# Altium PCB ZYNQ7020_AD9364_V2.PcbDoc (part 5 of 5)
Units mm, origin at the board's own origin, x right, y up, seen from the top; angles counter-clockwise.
Board outline 88.95 x 91.52 mm, 4 copper layers (Top Layer, Layer 1, Layer 2, Bottom Layer), stack 0.603 mm thick; 285 components, 278 nets, 1497 pads, 1247 vias.
Unrouted connection lines stored in the file: 367.
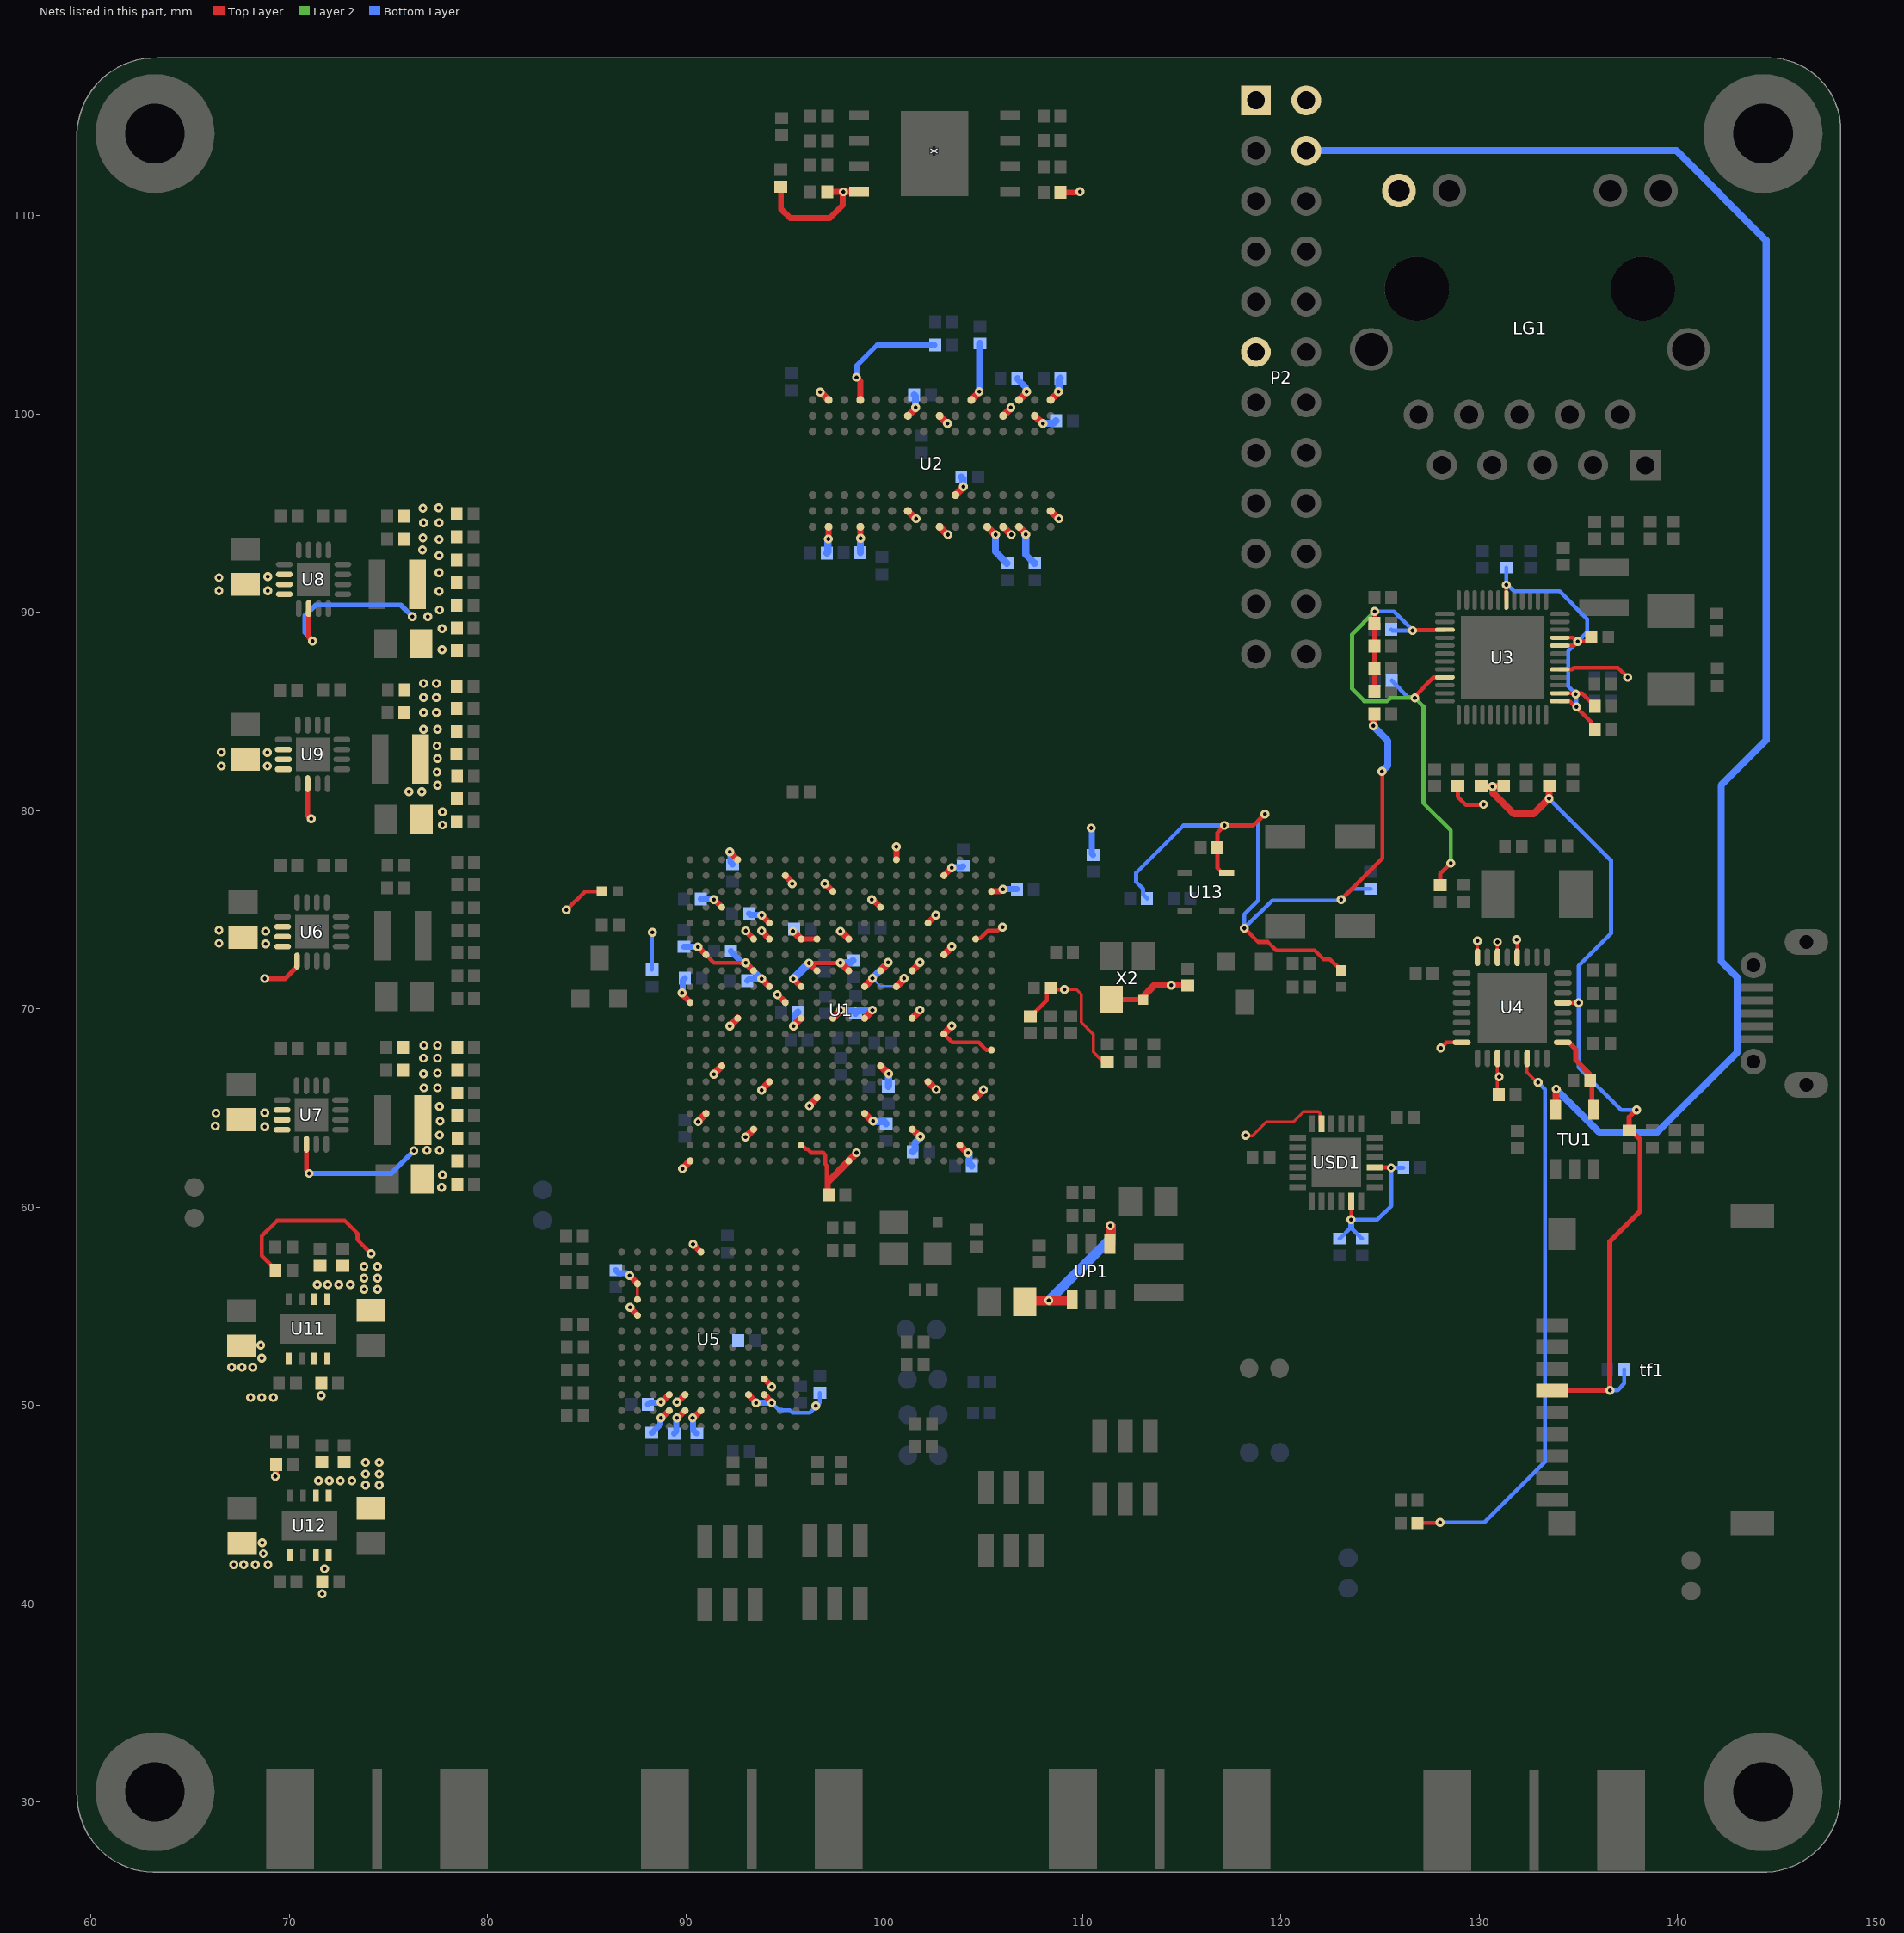
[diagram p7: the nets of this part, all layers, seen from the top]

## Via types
v1: diameter 0.45, hole 0.2, Top Layer to Bottom Layer, tented both sides, 995 vias
v2: diameter 0.406, hole 0.254, Top Layer to Bottom Layer, tented both sides, 118 vias
v3: diameter 1, hole 0.5, Top Layer to Bottom Layer, 116 vias
v4: diameter 0.5, hole 0.3, Top Layer to Bottom Layer, tented both sides, 16 vias
v5: diameter 0.406, hole 0.254, Top Layer to Bottom Layer, 2 vias

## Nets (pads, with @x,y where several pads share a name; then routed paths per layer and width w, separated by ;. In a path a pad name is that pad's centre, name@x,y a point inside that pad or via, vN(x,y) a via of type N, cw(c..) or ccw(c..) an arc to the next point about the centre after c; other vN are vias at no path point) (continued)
VCC_1V5: C8.2 C81.1 C98.1 C99.1 C100.1 C101.1 C102.1 C103.1 C104.1 C105.1 C106.1 C107.1 C108.1 C159.2 C160.2 C161.2 C187.2 C188.2 C189.2 C190.2 C191.2 C192.2 C193.2 L3.2 R3.1 R4.2 R13.1 R14.1 U1.A3 U1.D2 U1.E5 U1.G1 U1.H4 U1.L3 U1.P2 U1.R5 U1.U1 U1.V4 U2.A1 U2.A8 U2.B2 U2.C1 U2.C9 U2.D2 U2.D9 U2.E9 U2.F1 U2.G7 U2.H2 U2.H9 U2.K2 U2.K8 U2.N1 U2.N9 U2.R1 U2.R9 U8.14 | length 46.1
  Top Layer w0.25: U8.14@70.97,90.188 70.97,88.745 v1@71.171,88.544
  Top Layer w0.305: v1@91.417,75.513 U1.V4@91.81,75.12 ; v1@92.217,77.913 U1.U1@92.61,77.52 ; v1@93.817,74.714 U1.R5@94.21,74.32 ; U1.P2@95.01,76.72 v1@95.403,76.328 ; v1@97.017,76.313 U1.L3@97.41,75.92 ; v1(97.18,93.701) 97.18,94.297 U2.R9@97.194,94.31 ; v1(98.603,101.854) 98.794,101.663 U2.N1@98.794,100.711 ; U2.N9@98.795,94.309 98.798,94.306 98.798,93.73 v1(98.802,93.726) ; v1@99.417,75.513 U1.H4@99.81,75.12 ; U1.G1@100.61,77.52 v1(100.609,78.181) ; U1.E5@102.21,74.327 v1@102.603,74.72 ; U1.D2@103.01,76.72 v1@103.403,77.113 ; U1.A3@105.41,75.92 105.418,75.929 105.862,75.929 105.955,76.022 v1(105.994,76.022)
  Top Layer w0.356: v1@96.801,101.104 U2.R1@97.194,100.711 ; U2.K8@101.194,95.111 v1@101.587,94.717 ; U2.K2@101.194,99.911 v1@101.587,100.304 ; U2.H9@102.794,94.31 v1@103.187,93.917 ; U2.H2@102.794,99.911 v1@103.188,99.518 ; U2.G7@103.594,95.91 v1@103.987,96.304 ; U2.F1@104.394,100.711 v1@104.787,101.104 ; U2.E9@105.194,94.31 v1@105.587,93.917 ; U2.D9@105.994,94.31 v1@106.387,93.917 ; U2.D2@105.994,99.911 v1@106.387,100.304 ; U2.C9@106.794,94.31 v1@107.187,93.917 ; U2.C1@106.794,100.711 v1@107.187,101.104 ; U2.B2@107.594,99.911 v1@107.987,99.517 ; U2.A8@108.394,95.111 v1@108.787,94.717 ; U2.A1@108.394,100.711 v1@108.787,101.104
  Bottom Layer w0.25: v1(71.166,88.547) 71.166,88.601 70.79,88.977 70.79,89.84 71.323,90.373 75.616,90.373 v1(76.2,89.789) ; v1(98.603,101.854) 98.619,101.87 98.619,102.454 99.644,103.48 R4.2@102.565,103.48
  Bottom Layer w0.305: C107.1@90.747,75.54 90.76,75.527 91.397,75.527 v1(91.41,75.513) ; v1@92.206,77.909 v1(92.21,77.913) 92.238,77.886 92.238,77.402 C104.1@92.354,77.285 C104.1@92.358,77.289 ; C81.1@93.186,74.803 93.247,74.741 93.782,74.741 v1(93.81,74.714) ; v1(103.403,77.12) 103.43,77.148 103.938,77.148 C106.1@103.988,77.197 ; v1(105.994,76.022) 106.007,76.035 106.674,76.035 C105.1@106.687,76.048 ; C102.1@106.705,101.803 106.705,101.778 107.159,101.324 107.159,101.158 v1(107.187,101.13) ; v1(110.439,79.121) 110.467,79.093 110.467,77.823 R3.1@110.541,77.749
  Bottom Layer w0.356: C161.2@97.097,92.989 97.162,93.054 97.162,93.683 v1(97.18,93.701) ; C160.2@98.799,93.015 98.801,93.016 98.801,93.724 v1(98.802,93.726) ; C103.1@101.505,100.965 101.569,100.901 101.569,100.347 v1(101.587,100.329) ; C100.1@103.886,96.825 103.969,96.742 103.969,96.347 v1(103.987,96.329) ; v1(104.787,101.13) 104.805,101.148 104.805,103.542 C99.1@104.826,103.563 ; v1(105.613,93.917) 105.613,93.059 106.05,92.622 106.05,92.597 106.172,92.475 C159.2@106.197,92.475 ; v1(107.137,93.929) 107.137,92.907 107.569,92.475 C98.1@107.594,92.475 ; v1(108.013,99.517) 108.031,99.535 108.539,99.535 108.661,99.658 C101.1@108.661,99.67 ; v1(108.787,101.13) 108.805,101.148 108.805,101.725 C108.1@108.883,101.803
  other v1: 102.603,74.727 99.365,75.514 95.352,76.302 97.01,76.313 77.699,88.113 77.699,89.179 76.987,89.789 77.572,90.119 77.546,91.059 77.546,91.999 77.546,92.862 76.708,93.142 77.546,93.675 76.733,93.751 103.213,93.917 106.413,93.917 76.759,94.513 77.546,94.513 101.613,94.717 108.813,94.717 76.733,95.25 77.521,95.275 103.189,99.518 106.387,100.329 96.775,101.104
VCC_1V8: C3.2 C61.2 C62.2 C68.2 C69.2 C70.2 C71.2 C72.2 C73.2 C74.2 C80.2 C82.2 C83.2 C85.2 C86.2 C87.2 C89.2 C90.2 C91.2 C96.2 C109.2 C110.2 C141.1 L2.2 R8.1 R10.1 R23.1 R29.2 R30.1 R33.2 R34.1 R39.2 R41.2 R43.2 R45.2 R71.2 U1.A13 U1.B16 U1.C19 U1.D12 U1.E15 U1.F8 U1.F11 U1.F18 U1.G9 U1.H8 U1.H14 U1.J9 U1.J11 U1.J17 U1.K8 U1.K20 U1.L11 U1.M8 U1.M16 U1.N9 U1.N11 U1.N19 U1.P10 U1.R9 U1.R15 U1.T8 U1.T18 U1.U11 U1.V14 U1.W7 U1.W17 U1.Y10 U1.Y20 U3.15 U3.21 U4.8 U4.11 U4.14 U4.28 U4.30 U4.32 U7.14 USD1.5 | length 130.6
  Top Layer w0.152: v1(109.084,70.977) 109.693,70.977 109.931,70.739 109.931,69.317 110.541,68.707 110.541,67.824 110.857,67.508 110.858,67.508 111.227,67.139 R23.1@111.252,67.139 ; v1@118.186,63.602 118.567,63.602 119.26,64.295 120.641,64.295 121.154,64.808 121.894,64.808 121.983,64.719 121.983,64.272 USD1.5@122.057,64.198 ; U4.32@129.924,72.603 v1@129.924,73.403 ; C141.1@130.924,65.659 U4.11@130.924,67.503 ; U4.30@130.924,72.603 v1@130.924,73.343 ; U4.28@131.924,72.603 v1@131.924,73.486 ; U4.14@132.424,67.503 132.424,66.789 v1@132.944,66.269
  Top Layer w0.2: U1.W7@91.01,72.72 91.417,72.314 v1(93.01,72.314)
  Top Layer w0.203: U1.N19@95.81,63.12 95.85,63.12 96.043,62.927 96.128,62.927 96.313,62.742 96.913,62.742 97.032,62.623 97.032,62.164 97.095,62.1 97.095,60.789 97.148,60.789 97.187,60.828 97.187,61.298 ; U1.D12@103.01,68.72 103.43,68.301 104.765,68.301 105.141,67.924 105.406,67.924 U1.A13@105.41,67.92 ; R29.2@107.373,69.618 107.398,69.618 108.202,70.421 108.202,70.82 108.358,70.977 v1(109.084,70.977) ; R45.2@124.722,86.012 R43.2@124.722,87.155 R39.2@124.722,88.298 R41.2@124.722,89.441 124.739,89.459 v1(124.739,90.043) ; v1(126.644,89.078) 126.67,89.103 128.261,89.103 U3.15@128.276,89.118 ; v1(126.765,85.689) 126.765,85.776 127.704,86.715 128.272,86.715 U3.21@128.276,86.718 ; R71.2@126.892,44.069 128.016,44.069 v1@128.041,44.094 ; R33.2@128.041,76.237 128.041,76.81 v1(128.575,77.343) ; v1(128.067,68.021) 128.349,68.303 U4.8@129.124,68.303 ; R34.1@128.931,81.218 128.931,80.692 129.337,80.286 130.197,80.286 v1(130.226,80.315)
  Top Layer w0.22: v1(96.21,72.306) 96.217,72.314 v1(97.791,72.314)
  Top Layer w0.25: U7.14@70.858,63.17 70.858,61.831 v1(70.993,61.697)
  Top Layer w0.305: v1(89.81,70.792) 89.838,70.764 89.838,70.705 90.21,70.333 U1.Y10@90.21,70.32 ; v1@90.617,73.114 U1.W7@91.01,72.72 ; v1@93.017,72.314 U1.T8@93.41,71.92 ; v1@93.817,71.513 U1.R9@94.21,71.12 ; v1@94.617,70.714 U1.P10@95.01,70.32 ; v1@95.417,71.513 U1.N9@95.81,71.12 ; v1(96.21,72.306) 96.217,72.306 96.603,71.92 U1.M8@96.61,71.92
  Top Layer w0.35: 97.187,61.298 U1.K20@98.21,62.32
  Top Layer w0.356: v1@89.83,61.941 U1.Y20@90.21,62.32 U1.Y20@90.223,62.334 ; v1@90.616,64.327 U1.W17@91.01,64.72 ; v1@91.417,66.727 U1.V14@91.81,67.12 ; v1(92.217,69.123) 92.217,69.127 U1.U11@92.61,69.52 ; v1(93.006,63.536) 93.026,63.536 U1.T18@93.41,63.92 U1.T18@93.423,63.934 ; v1@93.817,65.927 U1.R15@94.21,66.32 ; v1(95.418,69.13) 95.419,69.13 U1.N11@95.81,69.52 ; v1(96.221,65.106) 96.221,65.131 U1.M16@96.61,65.52 ; U1.L11@97.41,69.52 v1@97.803,69.914 ; v1@97.817,72.314 U1.K8@98.21,71.92 ; U1.K20@98.21,62.32 v1@98.603,62.714 ; U1.J17@99.01,64.72 v1@99.403,64.327 ; U1.J11@99.01,69.52 v1@99.403,69.914 ; U1.J9@99.01,71.12 v1@99.403,71.514 ; U1.H14@99.81,67.12 v1@100.203,66.727 ; U1.H8@99.81,71.92 v1@100.203,72.314 ; U1.G9@100.61,71.12 v1@101.003,71.514 ; U1.F18@101.41,63.92 101.43,63.92 101.803,63.547 v1(101.829,63.547) ; U1.F11@101.41,69.52 v1@101.803,69.914 ; U1.F8@101.41,71.92 v1@101.816,72.326 ; U1.E15@102.21,66.32 v1@102.603,65.927 ; U1.D12@103.01,68.72 v1@103.403,69.114 ; U1.C19@103.81,63.12 v1@104.203,62.727 ; U1.B16@104.61,65.52 105.003,65.914 v1(105.003,65.924)
  Layer 2 w0.203: v1(124.739,90.043) 123.596,88.9 123.596,86.131 124.206,85.522 125.368,85.522 125.536,85.689 v1(126.765,85.689) 127.196,85.257 127.196,80.372 128.575,78.994 v1(128.575,77.343) ; v1@130.142,80.34 130.168,80.315 v1(130.226,80.315)
  Bottom Layer w0.107: v1(99.403,71.539) 99.797,71.145 100.61,71.145 v1(101.003,71.539)
  Bottom Layer w0.203: v1(124.739,90.043) 125.705,90.043 126.644,89.103 v1(126.644,89.078) 125.63,89.078 C110.2@125.572,89.136 ; C109.2@125.597,86.571 125.597,86.546 126.414,85.729 126.725,85.729 v1(126.765,85.689) ; v1(128.032,44.088) 130.27,44.088 133.325,47.142 133.325,65.933 v1(132.974,66.284)
  Bottom Layer w0.25: v1(70.993,61.697) 75.133,61.697 v1(76.276,62.84)
  Bottom Layer w0.305: v1(89.81,70.792) 89.838,70.819 89.838,71.441 C82.2@89.948,71.552 ; C83.2@89.891,73.133 89.9,73.124 90.6,73.124 v1(90.61,73.114) ; C73.2@92.271,72.923 92.271,72.898 v1@92.828,72.341 ; v1(93.01,72.314) v1(93.81,71.513) 93.782,71.486 93.152,71.486 C72.2@93.091,71.425
  Bottom Layer w0.356: v1(95.418,69.13) 95.418,69.156 95.527,69.265 95.527,69.702 C96.2@95.65,69.825 ; v1(97.791,72.314) 97.809,72.332 98.323,72.332 C70.2@98.425,72.434 ; v1(97.803,69.939) 97.829,69.939 97.865,69.903 98.43,69.903 C69.2@98.552,69.781 98.674,69.903 99.341,69.903 99.377,69.939 v1(99.403,69.939) ; v1(99.403,71.539) v1(100.203,72.339) ; v1(99.429,64.327) 99.447,64.309 99.997,64.309 C80.2@100.101,64.204 ; C68.2@100.203,66.084 100.216,66.097 100.216,66.714 v1(100.229,66.727) ; C90.2@101.429,62.789 101.551,62.911 101.551,63.244 101.829,63.522 v1(101.829,63.547) ; v1(104.229,62.727) 104.229,62.701 104.29,62.64 104.29,62.2 C85.2@104.413,62.078
  Bottom Layer w0.4: v1(95.41,71.513) 95.414,71.513 96.207,72.306 v1(96.21,72.306)
  other v1: 77.673,60.985 77.724,61.62 89.83,61.936 98.603,62.739 76.937,62.865 77.572,62.865 77.572,63.627 118.23,63.615 90.616,64.302 77.597,64.338 77.572,65.075 93.817,65.902 102.629,65.927 76.784,66.015 77.47,66.015 131.013,66.573 91.417,66.701 76.759,66.726 77.47,66.751 76.759,67.513 77.47,67.513 76.784,68.148 77.47,68.148 103.403,69.139 101.803,69.939 94.61,70.714 101.803,72.339 130.93,73.368 129.914,73.419 131.895,73.495
VCC_3V3: *.8 C9.2 C20.2 C21.2 C25.2 C26.2 C75.2 C76.2 C77.2 C78.2 C113.2 C114.2 C115.2 C116.2 C120.1 C132.1 C133.1 C134.1 C138.1 C139.1 C181.1 C182.1 C183.1 CP1.2 DONE.1 L4.2 LG1.14 P2.1 P2.6 R15.1 R16.1 R19.1 R27.2 R35.1 R38.1 R46.1 R47.1 R48.1 R55.1 R57.1 R59.2 R63.1 R68.2 tf1.4 U1.B6 U1.D7 U1.K6 U1.M6 U1.N6 U1.R6 U1.T6 U3.6 U3.37 U3.38 U3.41 U3.44 U3.45 U4.21 U9.14 U11.5 U11.7 U11.8 U12.5 U12.7 U12.8 U13.4 UP1.1 UP1.4 USD1.17 USD1.21 USR_LED.1 X2.1 X2.4 | length 150.6
  Top Layer w0.2: v1(118.161,74.066) 118.855,73.372 119.344,73.372 119.767,72.949 121.706,72.949 122.161,72.493 122.484,72.493 USR_LED.1@123.038,71.94
  Top Layer w0.203: v1(83.972,74.981) 84.912,75.921 DONE.1@85.747,75.921 ; U1.B6@104.61,73.52 104.638,73.548 104.841,73.548 105.235,73.942 105.727,73.942 105.902,74.117 v1(105.969,74.117) ; v1(117.164,79.249) 118.619,79.249 v1(119.202,79.832) ; v1@117.17,79.248 116.808,78.886 C132.1@116.808,78.13 116.808,77.096 117.043,76.86 U13.4@117.272,76.86 ; v1(123.038,75.514) 125.12,77.597 v1@125.12,81.94 ; v1@123.556,59.385 USD1.17@123.556,60.3 ; USD1.21@124.757,61.999 125.575,61.999 v1@125.578,62.001 ; v1@131.369,91.415 131.376,91.408 U3.6@131.376,90.618 ; U3.37@134.076,85.518 134.079,85.515 134.584,85.515 135.642,84.458 135.642,84.305 C115.2@135.84,84.107 ; U3.38@134.076,85.918 135.197,85.918 135.84,85.275 C116.2@135.84,85.25 ; U3.41@134.076,87.118 134.079,87.121 134.693,87.121 134.774,87.202 137.004,87.202 v1(137.49,86.716) ; U3.44@134.076,88.318 134.079,88.321 134.778,88.321 134.909,88.452 v1@134.909,88.544 ; U3.45@134.076,88.718 134.079,88.715 134.738,88.715 v1@134.909,88.544 ; U4.21@134.224,70.303 v1(135.022,70.303) ; C114.2@135.661,88.748 135.661,88.743 135.463,88.544 v1@134.909,88.544
  Top Layer w0.25: U9.14@70.922,81.354 70.922,79.751 v1(71.095,79.578) ; X2.4@111.455,70.46 112.903,70.46 X2.1@113.055,70.46 ; tf1.4@133.685,50.741 133.693,50.749 136.585,50.749 v1(136.594,50.758) 136.594,58.26 138.118,59.784 138.118,63.406 R68.2@137.643,63.881 ; R68.2@137.566,63.856 137.566,64.538 137.922,64.894 v1@137.922,64.948
  Top Layer w0.254: U1.N6@95.81,73.52 U1.M6@96.61,73.52
  Top Layer w0.3: R48.1@94.793,111.462 94.793,110.338 95.25,109.88 97.257,109.88 97.907,110.531 97.907,111.179 v1(97.935,111.206) ; C133.1@97.13,111.201 97.135,111.206 v1(97.935,111.206) ; *.8@98.74,111.211 98.735,111.206 v1(97.935,111.206) ; R59.2@108.883,111.176 v1@109.804,111.176
  Top Layer w0.305: v1(93.01,73.936) 93.01,73.928 93.41,73.528 U1.T6@93.41,73.52 ; v1(93.81,73.936) 93.81,73.928 94.21,73.528 U1.R6@94.21,73.52
  Top Layer w0.356: v1@95.417,73.914 U1.N6@95.81,73.52 ; v1@97.817,73.914 U1.K6@98.21,73.52 ; U1.D7@103.01,72.72 v1@103.403,73.114 ; X2.1@112.903,70.46 112.975,70.532 113.64,71.196 v1(114.469,71.196) 115.297,71.196 C120.1@115.316,71.178 ; v1(124.663,84.277) 124.663,84.811 R38.1@124.722,84.869 ; R27.2@130.1,81.218 v1(130.671,81.218) ; R35.1@131.243,81.218 v1(130.671,81.218) ; R46.1@133.554,81.218 133.528,81.192 133.528,80.62 132.745,79.837 131.748,79.837 130.689,80.895 130.689,81.2 v1(130.671,81.218)
  Top Layer w0.5: CP1.2@107.088,55.22 107.149,55.28 v1(108.301,55.28) 109.454,55.28 109.479,55.305 UP1.1@109.479,55.341 ; UP1.4@111.379,58.141 111.404,58.166 v1(111.404,59.055)
  Bottom Layer w0.2: v1(119.202,79.832) 118.847,79.477 118.847,75.463 118.161,74.778 v1(118.161,74.066) 119.563,75.469 122.992,75.469 v1(123.038,75.514)
  Bottom Layer w0.203: R55.1@88.29,71.977 88.29,73.838 v1@88.316,73.863 ; R47.1@113.252,75.565 113.053,75.763 113.053,76.05 112.703,76.4 112.703,76.86 115.092,79.249 v1(117.164,79.249) ; C138.1@122.961,58.413 122.986,58.413 123.501,58.928 123.501,59.316 v1(123.549,59.363) ; v1(123.038,75.514) 123.578,76.054 R19.1@124.536,76.054 ; C134.1@124.104,58.413 124.079,58.413 123.596,58.897 123.596,59.316 v1(123.549,59.363) ; C139.1@126.187,61.976 126.184,61.979 v1(125.57,61.979) 125.57,60.064 124.869,59.363 v1(123.549,59.363) ; C113.2@131.369,92.253 131.371,92.251 v1(131.371,91.38) 131.437,91.38 131.759,91.059 134.061,91.059 135.458,89.662 135.458,89.012 v1(134.968,88.522) 134.493,88.047 134.493,86.258 v1(134.874,85.877) 134.896,85.856 134.896,85.242 v1(134.918,85.22) ; v1(133.53,80.611) 136.652,77.49 136.652,73.787 135.022,72.157 v1(135.022,70.303) 135.022,67.035 137.16,64.897 v1(137.947,64.897) ; v1@136.594,50.759 136.985,50.759 137.324,51.098 R63.1@137.324,51.816
  Bottom Layer w0.356: v1(124.663,84.277) 124.663,84.252 125.4,83.515 125.4,82.271 v1(125.095,81.966)
  Bottom Layer w0.5: v1(108.301,55.28) 111.404,58.383 v1(111.404,59.055)
  other v1: 71.653,40.488 71.78,41.758 67.191,41.971 67.699,41.971 68.283,41.971 68.918,41.971 68.682,42.52 68.631,43.078 68.047,50.394 68.605,50.394 69.19,50.394 71.603,50.495 67.081,51.918 67.615,51.918 68.148,51.918 68.605,52.375 68.555,53.035 103.403,73.139 88.309,73.864 95.391,73.914 97.791,73.914 77.724,79.273 77.724,79.934 76.022,80.95 76.683,80.95 77.47,81.28 77.445,81.94 77.47,82.626 77.445,83.261 76.759,84.099 77.47,84.099 76.759,84.938 77.419,84.938 76.759,85.7 77.419,85.7 76.759,86.411 77.419,86.411 109.864,111.212
VCC_IN: C4.2 C5.2 C10.2 C12.2 P2.13 P2.14 TU1.5 U6.10 U6.11 U6.12 U6.13 U7.10 U7.11 U7.12 U8.10 U8.11 U8.12 U9.10 U9.11 U9.12 | length 82.2
  Top Layer w0.25: v1(68.758,71.526) 69.783,71.526 70.383,72.127 U6.13@70.383,72.413
  Top Layer w0.356: TU1.5@133.873,64.905 v1@133.873,65.954
  Bottom Layer w0.356: P2.14@121.285,113.284 139.954,113.284 144.475,108.763 144.475,83.541 142.215,81.28 142.215,72.39 143.027,71.577 143.027,67.818 138.989,63.779 136.057,63.779 v1(133.886,65.951)
  other v1: 68.758,64.059 66.269,64.084 66.294,64.719 68.758,64.745 68.809,73.279 66.446,73.304 68.809,73.914 66.446,73.965 66.573,82.245 68.885,82.245 68.885,82.931 66.573,82.956 66.446,91.084 68.91,91.084 66.446,91.745 68.91,91.796
VDD_DIG: C22.2 C23.2 C24.2 C172.1 C177.1 R22.1 RX4.2 U5.B8 U5.D2 U5.D3 U5.E3 U5.F12 U5.K4 U12.1 U12.2 | length 5.5
  Top Layer w0.3: v1(69.291,46.406) 69.311,46.425 69.311,46.996 R22.1@69.33,47.015
  Top Layer w0.305: v1@87.181,54.907 U5.B8@87.554,54.534 ; v1@88.767,49.361 U5.D2@89.141,49.734 ; v1@88.767,50.161 U5.D3@89.141,50.534 ; v1@89.567,50.161 U5.E3@89.941,50.534 ; v1(90.357,58.131) U5.F12@90.754,57.734 ; U5.K4@93.954,51.334 v1@94.328,50.961
  Bottom Layer w0.3: C177.1@88.08,50.038 88.175,50.132 88.707,50.132 v1(88.735,50.161) ; C172.1@88.265,48.609 88.29,48.609 88.707,49.026 88.707,49.332 v1(88.735,49.361)
  other v1: 73.838,45.974 74.524,45.974 71.476,46.203 72.009,46.203 72.568,46.203 73.152,46.203 73.838,46.533 74.524,46.533 73.838,47.117 74.524,47.117 89.536,50.161 94.328,50.929 87.181,54.939
VDDA_RX_LO: C17.2 C18.2 C19.2 C166.1 C170.1 C174.1 C175.1 R21.1 U5.B9 U5.B10 U5.E2 U5.F2 U5.J3 U5.K3 U11.1 U11.2 | length 18.9
  Top Layer w0.15: U5.B9@87.554,55.334 U5.B10@87.554,56.134
  Top Layer w0.2: R21.1@69.298,56.82 69.298,56.845 68.605,57.537 68.605,58.536 69.379,59.309 72.799,59.309 73.434,58.674 73.434,58.341 v1(74.117,57.658)
  Top Layer w0.305: v1(87.16,56.544) 87.16,56.536 87.55,56.147 U5.B10@87.554,56.147 ; v1@89.567,49.361 U5.E2@89.941,49.734 ; v1@90.367,49.361 U5.F2@90.74,49.734 ; U5.J3@93.154,50.534 v1@93.527,50.161 ; U5.K3@93.954,50.534 v1@94.328,50.161
  Bottom Layer w0.2: v1(94.328,50.129) 94.346,50.129 94.346,50.11 94.701,49.756 95.239,49.756 95.375,49.619 96.254,49.619 96.491,49.856 v1(96.546,49.963) ; v1@96.572,49.937 96.749,50.114 C166.1@96.749,50.629
  Bottom Layer w0.305: C170.1@86.462,56.813 86.609,56.665 87,56.665 87.121,56.544 v1(87.16,56.544) ; C175.1@89.408,48.577 89.508,48.676 89.508,49.333 v1(89.536,49.361) ; v1(90.335,49.361) 90.363,49.333 90.363,48.771 90.378,48.756 90.378,48.731 90.526,48.583 C174.1@90.551,48.583 ; v1(93.527,50.129) v1(94.328,50.129)
  other v1: 73.762,55.855 74.447,55.855 71.399,56.083 71.933,56.083 72.492,56.083 73.076,56.083 73.762,56.413 74.447,56.413 73.762,56.998 74.447,56.998
VUSB_V_EN: R69.1 TU1.4 U4.17 | length 4.2
  Top Layer w0.254: U4.17@134.224,68.303 134.527,68.303 134.874,67.956 134.874,67.412 135.582,66.704 135.582,66.392 R69.1@135.604,66.37 135.688,66.286 135.688,64.99 TU1.4@135.773,64.905
pads on no net: *.9 LG1. tf1.0 tf1.11 tf1.12 U1.A20 U1.B5 U1.B9 U1.B13 U1.B19 U1.B20 U1.C6 U1.C20 U1.D9 U1.D18 U1.D19 U1.E6 U1.E8 U1.E9 U1.E17 U1.E18 U1.E19 U1.F16 U1.F17 U1.F19 U1.G14 U1.G15 U1.G17 U1.G18 U1.G19 U1.H15 U1.H16 U1.H17 U1.H18 U1.J14 U1.J15 U1.J16 U1.J18 U1.J19 U1.K9 U1.K14 U1.K16 U1.K17 U1.K18 U1.K19 U1.L10 U1.L14 U1.L15 U1.L16 U1.L17 U1.L19 U1.L20 U1.M14 U1.M15 U1.M17 U1.M18 U1.M19 U1.M20 U1.N15 U1.N16 U1.P1 U1.P3 U1.R1 U1.R2 U1.R3 U1.T1 U1.T2 U1.T4 U1.T5 U1.T9 U1.U2 U1.U3 U1.U4 U1.U5 U1.U7 U1.U8 U1.U9 U1.U10 U1.V1 U1.V2 U1.V3 U1.V5 U1.V6 U1.V7 U1.V8 U1.V10 U1.V11 U1.W1 U1.W3 U1.W4 U1.W5 U1.W6 U1.W8 U1.W9 U1.W10 U1.W11 U1.W15 U1.Y1 U1.Y2 U1.Y3 U1.Y4 U1.Y6 U1.Y7 U1.Y8 U1.Y9 U1.Y11 U1.Y12 U1.Y13 U2.J1 U2.J9 U2.L1 U2.L9 U2.M7 U3.12 U3.46 U4.12 U4.15 U4.16 U5.A3 U5.B3 U5.B4 U5.B5 U5.B6 U5.B7 U5.C3 U5.L5 U5.M3 U5.M11 UP1.5 USD1.8 USD1.10 USD1.12 USD1.13 USD1.14 USD1.15 X4.1
copper on no net:
  other v1: 103.48,111.735 101.676,111.76 101.651,114.427 103.48,114.427
  other v3: 63.221,28.305 63.221,28.305 144.323,28.305 144.323,28.305 62.379,28.473 62.379,28.473 64.063,28.473 64.063,28.473 143.481,28.473 143.481,28.473 145.165,28.473 145.165,28.473 61.665,28.95 61.665,28.95 64.776,28.95 64.776,28.95 142.767,28.95 142.767,28.95 145.878,28.95 145.878,28.95 61.188,29.663 61.188,29.663 65.253,29.663 142.29,29.663 142.29,29.663 146.355,29.663 61.021,30.505 61.021,30.505 65.421,30.505 142.123,30.505 142.123,30.505 146.523,30.505 61.188,31.347 61.188,31.347 65.253,31.347 142.29,31.347 142.29,31.347 146.355,31.347 61.665,32.061 61.665,32.061 64.776,32.061 64.776,32.061 142.767,32.061 142.767,32.061 145.878,32.061 145.878,32.061 62.379,32.538 62.379,32.538 64.063,32.538 64.063,32.538 143.481,32.538 143.481,32.538 145.165,32.538 145.165,32.538 63.221,32.705 63.221,32.705 144.323,32.705 144.323,32.705 63.221,111.948 63.221,111.948 144.323,111.948 144.323,111.948 62.379,112.115 62.379,112.115 64.063,112.115 64.063,112.115 143.481,112.115 143.481,112.115 145.165,112.115 145.165,112.115 61.665,112.592 61.665,112.592 64.776,112.592 64.776,112.592 142.767,112.592 142.767,112.592 145.878,112.592 145.878,112.592 61.188,113.306 61.188,113.306 65.253,113.306 142.29,113.306 142.29,113.306 146.355,113.306 61.021,114.148 61.021,114.148 65.421,114.148 142.123,114.148 142.123,114.148 146.523,114.148 61.188,114.99 61.188,114.99 65.253,114.99 142.29,114.99 142.29,114.99 146.355,114.99 61.665,115.703 61.665,115.703 64.776,115.703 64.776,115.703 142.767,115.703 142.767,115.703 145.878,115.703 145.878,115.703 62.379,116.18 62.379,116.18 64.063,116.18 64.063,116.18 143.481,116.18 143.481,116.18 145.165,116.18 145.165,116.18 63.221,116.348 63.221,116.348 144.323,116.348 144.323,116.348

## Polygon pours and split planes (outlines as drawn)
GND on Top Layer "GND_L01_P155" (solid, pour order 155): 71.222,63.475 71.984,63.475 71.984,62.789 72.644,62.128 75.514,62.128 75.514,60.655 72.619,60.655 71.222,62.052
GND on Top Layer "GND_L01_P147" (solid, pour order 147): 141.478,41.478 139.776,41.478 139.548,41.707 139.548,42.926 139.827,43.205 141.3,43.205 141.681,42.824 141.681,41.656
GND on Top Layer "GND_L01_P146" (solid, pour order 146): 119.304,51.003 119.304,52.705 119.532,52.934 120.752,52.934 121.031,52.654 121.031,51.181 120.65,50.8 119.482,50.8
GND on Top Layer "GND_L01_P145" (solid, pour order 145): 65.964,60.274 64.262,60.274 64.033,60.503 64.033,61.722 64.313,62.001 65.786,62.001 66.167,61.62 66.167,60.452
RFGND on Top Layer "RFGND_L01_P142" (solid, pour order 142): 146.253,34.646 143.013,34.646 ccw(c143.013,32.106) 141.217,33.902 140.538,33.223 ccw(c141.029,32.733) 140.335,32.733 140.335,27.94 cw(c138.618,27.94) 139.832,26.726 139.802,26.695 cw(c139.556,26.941) 139.556,26.594 67.278,26.594 cw(c67.278,27.374) 66.726,26.822 cw(c66.91,27.006) 66.65,27.006 66.65,31.13 ccw(c64.11,31.13) 65.906,32.926 65.024,33.807 ccw(c63.859,32.642) 63.859,34.29 62.154,34.29 cw(c62.154,36.007) 60.94,34.793 60.604,35.128 cw(c61.463,35.987) 60.249,35.987 60.249,56.682 cw(c62.789,56.682) 60.993,58.478 61.824,59.309 cw(c63.602,57.531) 63.602,60.046 115.026,60.046 cw(c115.026,57.506) 116.822,59.302 118.28,57.843 cw(c116.485,56.047) 119.024,56.047 119.024,45.782 ccw(c121.564,45.782) 119.768,43.985 121.59,42.164 ccw(c123.368,43.942) 123.368,41.427 142.322,41.427 146.631,41.427 cw(c141.432,37.309) 147.879,35.752 147.456,35.197 147.355,35.087 cw(c146.228,36.214) 146.228,34.62
VCC_3V3 on Top Layer "VCC_3V3_L01_P130" (solid, pour order 130): 71.603,50.089 67.767,50.089 67.716,50.14 67.716,50.622 67.767,50.673 71.222,50.673 71.603,51.054
VCC_3V3 on Top Layer "VCC_3V3_L01_P091" (solid, pour order 91): 71.12,52.756 72.085,52.756 72.085,51.587 71.907,51.41 71.907,50.089 71.298,50.089 71.298,51.867 71.12,52.045
GND on Top Layer "GND_L01_P125" (solid, pour order 125): 68.301,65.634 68.301,67.437 67.996,67.742 66.345,67.742 66.167,67.564 66.167,65.837 66.37,65.634
GND on Top Layer "GND_L01_P124" (solid, pour order 124): 68.377,74.803 68.377,76.606 68.072,76.911 66.421,76.911 66.243,76.733 66.243,75.006 66.446,74.803
GND on Top Layer "GND_L01_P123" (solid, pour order 123): 68.478,83.769 68.478,85.573 68.174,85.877 66.523,85.877 66.345,85.7 66.345,83.972 66.548,83.769
GND on Top Layer "GND_L01_P122" (solid, pour order 122): 68.504,92.608 68.504,94.412 68.199,94.717 66.548,94.717 66.37,94.539 66.37,92.812 66.573,92.608
VCC_IN on Top Layer "VCC_IN_L01_P121" (solid, pour order 121): 69.952,65.024 69.952,63.754 65.989,63.754 65.989,65.024
VCC_IN on Top Layer "VCC_IN_L01_P120" (solid, pour order 120): 70.053,74.27 70.053,73 66.142,73 66.142,74.27
VCC_IN on Top Layer "VCC_IN_L01_P119" (solid, pour order 119): 70.079,83.21 70.079,81.94 66.294,81.94 66.294,83.21
VCC_IN on Top Layer "VCC_IN_L01_P118" (solid, pour order 118): 70.028,92.05 70.028,90.78 66.167,90.78 66.167,92.05
GND on Top Layer "GND_L01_P116" (solid, pour order 116): 71.247,72.695 72.009,72.695 72.009,72.085 72.746,71.349 75.489,71.349 75.489,69.875 72.593,69.875 71.247,71.222
GND on Top Layer "GND_L01_P115" (solid, pour order 115): 71.272,81.686 72.06,81.686 72.06,80.975 72.746,80.289 75.438,80.289 75.438,78.816 72.542,78.816 71.272,80.086
GND on Top Layer "GND_L01_P114" (solid, pour order 114): 71.323,90.5 72.085,90.5 72.085,89.865 72.796,89.154 75.438,89.154 75.438,87.681 72.542,87.681 71.323,88.9
NetL2_1 on Top Layer "NETL2_1_L01_P113" (solid, pour order 113): 72.314,65.024 72.314,63.754 73.635,63.754 74.244,63.144 75.108,63.144 75.108,65.634 74.27,65.634 73.66,65.024
NetL1_1 on Top Layer "NETL1_1_L01_P112" (solid, pour order 112): 72.314,74.27 72.314,73 73.711,73 74.27,72.441 75.133,72.441 75.133,74.93 74.295,74.93 73.635,74.27
NetL4_1 on Top Layer "NETL4_1_L01_P111" (solid, pour order 111): 72.339,83.21 72.339,81.94 73.533,81.94 74.117,81.356 74.981,81.356 74.981,83.845 74.143,83.845 73.508,83.21
NetL3_1 on Top Layer "NETL3_1_L01_P110" (solid, pour order 110): 72.39,92.05 72.39,90.78 73.381,90.78 73.99,90.17 74.854,90.17 74.854,92.659 74.016,92.659 73.406,92.05
GND on Top Layer "GND_L01_P109" (solid, pour order 109): 70.104,68.351 72.009,68.351 72.009,67.361 71.501,66.853 71.501,65.786 70.206,65.786 70.206,66.853 70.104,66.954
GND on Top Layer "GND_L01_P108" (solid, pour order 108): 70.104,77.546 72.034,77.546 72.034,76.53 71.526,76.022 71.526,75.032 70.231,75.032 70.231,76.048 70.104,76.175
GND on Top Layer "GND_L01_P107" (solid, pour order 107): 72.009,86.411 70.079,86.411 70.079,85.344 70.282,85.141 70.282,83.972 71.552,83.972 71.552,84.988 72.009,85.446
GND on Top Layer "GND_L01_P106" (solid, pour order 106): 70.333,92.837 71.603,92.837 71.603,93.828 72.009,94.234 72.009,95.174 70.104,95.174 70.104,93.929 70.333,93.701
GND on Top Layer "GND_L01_P105" (solid, pour order 105): 78.892,69.419 78.892,68.504 79.045,68.351 79.045,60.884 79.197,60.731 80.467,60.731 82.829,63.094 82.829,69.673
GND on Top Layer "GND_L01_P104" (solid, pour order 104): 83.194,83.398 82.333,82.536 81.798,83.285 82.412,83.49
GND on Top Layer "GND_L01_P103" (solid, pour order 103): 78.892,95.352 79.273,95.733 82.474,95.733 82.702,95.961 82.829,95.834 82.829,69.571 82.093,68.834 79.375,68.834 78.892,69.317
GND on Top Layer "Top Layer-GND" (solid, pour order 76): 88.154,83.582 88.154,92.024 89.002,92.812 89.029,98.559 94.302,103.832 101.076,103.832 102.925,101.983 109.574,101.983 112.973,98.584 112.973,81.038 107.949,76.014 107.949,75.794 111.827,75.794 112.098,76.064 112.098,77.089 115.646,80.637 115.646,104.008 110.536,109.118 90.297,109.118 82.677,101.498 82.677,83.109 87.681,83.109
VCC_1V5 on Top Layer "VCC_1V5_L01_P102" (solid, pour order 102): 78.791,87.655 75.87,87.655 75.794,87.732 75.794,92.735 75.413,93.116 75.413,95.631 75.514,95.733 78.74,95.733 78.791,95.682
VCC_3V3 on Top Layer "VCC_3V3_L01_P101" (solid, pour order 101): 75.794,78.689 75.717,78.765 75.717,84.099 75.438,84.379 75.438,86.69 75.565,86.817 78.791,86.817 78.867,86.741 78.867,78.791 78.765,78.689
VCC_1V0 on Top Layer "VCC_1V0_L01_P100" (solid, pour order 100): 75.971,69.698 75.819,69.85 75.819,75.133 75.413,75.54 75.413,78.105 75.59,78.283 78.791,78.283 78.791,69.774 78.715,69.698
VCC_1V8 on Top Layer "VCC_1V8_L01_P098" (solid, pour order 98): 78.816,60.757 77.546,60.757 77.419,60.63 75.971,60.63 75.87,60.731 75.87,65.862 75.336,66.396 75.336,68.402 75.463,68.529 78.791,68.529 78.816,68.504
VCC_3V3 on Top Layer "VCC_3V3_L01_P093" (solid, pour order 93): 70.206,42.748 69.342,42.748 68.428,43.663 66.878,43.663 66.878,41.707 70.206,41.707
VCC_3V3 on Top Layer "VCC_3V3_L01_P092" (solid, pour order 92): 70.129,52.654 69.266,52.654 68.351,53.569 66.802,53.569 66.802,51.638 70.129,51.638
VCC_3V3 on Top Layer "VCC_3V3_L01_P090" (solid, pour order 90): 71.171,42.774 72.136,42.774 72.136,41.605 71.958,41.427 71.958,40.208 71.349,40.208 71.349,41.986 71.171,42.164
VDD_DIG on Top Layer "VDD_DIG_L01_P089" (solid, pour order 89): 71.145,45.085 71.145,47.447 74.727,47.447 74.854,47.32 74.854,44.221 73.254,44.221 72.39,45.085
VDDA_RX_LO on Top Layer "VDDA_RX_LO_L01_P088" (solid, pour order 88): 71.12,55.042 71.12,57.404 74.778,57.404 74.905,57.277 74.905,54.178 73.304,54.178 72.441,55.042
REG_OUT on Top Layer "REG_OUT_L01_P079" (solid, pour order 79): 133.604,89.819 137.533,89.819 137.533,90.759 133.774,90.759 133.604,90.759
VCC_3V3 on Layer 2 "VCC_3V3_L03_P134" (solid, pour order 134): 114.989,81.741 114.989,89.09 116.51,90.611 116.51,116.357 117.653,117.5 145.694,117.5 147.599,115.595 147.599,82.321 147.019,81.741
VCC_3V3 on Layer 2 "VCC_3V3_L03_P137" (solid, pour order 137): 92.964,117.5 62.636,117.5 59.69,114.554 59.69,30.226 63.221,26.695 145.644,26.695 147.98,30.318 147.98,103.581 134.188,117.373
VCC_1V8 on Layer 2 "VCC_1V8_L03_P136" (solid, pour order 136): 103.53,60.071 122.84,60.071 147.295,60.071 147.676,60.452 147.676,80.874 146.609,81.94 125.4,81.94 114.478,71.018 113.36,71.018 111.768,72.61 105.613,72.61
VCC_3V3 on Layer 2 "VCC_3V3_L03_P135" (solid, pour order 135): 116.637,108.791 116.232,109.195 93.929,109.195 92.837,110.287 92.837,117.094 93.269,117.526 117.656,117.526
VCC_3V3 on Layer 2 "VCC_3V3_L03_P133" (solid, pour order 133): 105.969,72.72 111.184,72.72 113.191,70.714 114.986,70.714 126.009,81.737 126.009,84.557 125.832,84.734 117.983,84.734 107.662,74.414 106.405,74.414
VDD_DIG on Layer 2 "VDD" (solid, pour order 129): 80.086,53.916 73.483,53.924 72.06,55.347 70.663,55.347 70.612,55.397 70.18,54.966 70.18,47.015 78.384,47.015 80.086,45.644
VCC_3V3 on Layer 2 "VCC_3V3_L03_P131" (solid, pour order 131): 76.098,78.816 75.641,78.359 75.616,78.359 75.616,69.672 74.955,69.012 74.955,60.427 74.498,59.969 69.52,59.969 68.859,59.309 68.859,49.276 74.701,43.434 74.701,39.827 74.397,39.522 61.671,39.522 61.366,39.827 61.366,82.626 65.507,86.766 75.997,86.766
VDD_DIG on Layer 2 "VDD_DIG_L03_P097" (solid, pour order 97): 69.113,46.203 69.113,49.708 71.018,49.708 71.018,47.447 75.108,47.447 75.26,47.295 75.26,44.272 75.133,44.145 73.101,44.145 71.374,45.872 69.444,45.872
VCC_1V5 on Layer 2 "MidLayer2-VCC-DDR" (solid, remove dead copper, pour order 78): 89.51,109.55 115.722,109.55 116.789,108.483 116.789,90.89 114.879,88.98 114.879,81.482 107.921,74.524 85.725,74.524 84.512,75.737 84.512,104.553
VCC_1V5 on Layer 2 "VCC_1V5_L03_P099" (solid, pour order 99): 85.776,84.531 83.439,86.868 76.2,86.868 75.717,87.351 75.717,97.18 76.53,97.993 84.226,97.993 84.633,98.4
VCC_1V0 on Layer 2 "VCC_1V0_L03_P084" (solid, pour order 84): 87.341,71.009 86.081,69.748 75.997,69.748 75.794,69.952 75.794,78.181 76.2,78.588 79.019,78.588 84.286,73.321 87.525,73.321
VCC_3V3 on Layer 2 "VCC_3V3_L03_P080" (solid, pour order 80): 102.985,72.72 106.528,72.72 106.655,72.847 106.655,74.164 106.396,74.422 85.496,74.422 82.753,77.165 81.051,77.165 80.848,76.962 84.379,73.431 87.274,73.431 102.273,73.431
VDD_DIG on Layer 2 "VDD_DIG_L03_P096" (solid, pour order 96): 69.113,59.334 69.113,49.708 71.018,49.708 71.018,57.963 84.176,57.963 84.201,57.988 83.744,59.792 69.571,59.792
VDD_DIG on Layer 2 "VDD_DIG_L03_P095" (solid, pour order 95): 84.48,59.792 84.709,59.792 98.196,59.792 98.196,46.457 97.384,45.644 79.883,45.644 79.883,59.792
VDDA_RX_LO on Layer 2 "VDDA_RX_LO_L03_P094" (solid, pour order 94): 87.033,57.861 71.374,57.861 71.12,57.607 71.12,55.347 71.45,55.016 72.517,55.016 73.508,54.026 85.242,54.026 87.01,55.793
VDDA_RX_LO on Layer 2 "VDDA_RX_LO_L03_P087" (solid, pour order 87): 86.716,57.709 86.716,55.753 86.842,55.626 89.687,55.626 90.703,54.61 90.703,50.801 90.423,50.521 91.757,50.521 91.757,50.711 91.618,50.851 91.618,56.261 90.018,57.861 86.868,57.861
VDDA_RX_LO on Layer 2 "VDDA_RX_LO_L03_P086" (solid, pour order 86): 94.615,49.835 94.437,49.657 91.262,49.657 90.526,48.92 89.357,48.92 89.205,49.073 89.205,49.505 90.373,50.673 94.412,50.673 94.615,50.47
VCC_1V8 on Layer 2 "VCC_1V8_L03_P085" (solid, pour order 85): 89.891,71.679 88.29,71.679 86.258,69.647 75.844,69.647 75.235,69.037 75.235,60.274 75.463,60.046 89.284,60.046 90.249,61.011
VCC_3V3 on Layer 2 "VCC_3V3_L03_P083" (solid, pour order 83): 82.345,75.44 78.969,78.816 76.098,78.816 75.768,79.146 75.768,86.538 75.997,86.766 83.236,86.766 84.303,85.7 84.303,74.617
VCC_1V8 on Layer 2 "VCC_1V8_L03_P082" (solid, pour order 82): 89.306,72.009 89.256,71.958 89.256,60.071 103.911,60.071 105.613,61.773 105.613,75.057 90.17,75.057 89.306,74.193
VCC_1V0 on Layer 2 "VCC_1V0_L03_P081" (solid, pour order 81): 93.337,67.242 93.396,67.183 101.244,67.183 101.473,67.412 101.473,73.152 101.044,73.58 87.652,73.58 85.903,71.831 85.903,71.095 86.131,70.866 87.198,70.866 88.138,71.806 99.771,71.806 99.898,71.679 99.898,69.621 99.661,69.384 93.337,69.384
GND on Bottom Layer "GND_L04_P150" (solid, pour order 150): 83.591,60.173 81.89,60.173 81.661,60.401 81.661,61.62 81.94,61.9 83.414,61.9 83.795,61.519 83.795,60.35
GND on Bottom Layer "GND_L04_P149" (solid, pour order 149): 124.282,41.707 122.58,41.707 122.352,41.935 122.352,43.155 122.631,43.434 124.104,43.434 124.485,43.053 124.485,41.885
GND on Bottom Layer "GND_L04_P148" (solid, pour order 148): 119.278,46.761 119.278,48.463 119.507,48.692 120.726,48.692 121.006,48.412 121.006,46.939 120.625,46.558 119.456,46.558
RFGND on Bottom Layer "RFGND_L04_P144" (solid, pour order 144): 146.279,34.646 143.038,34.646 ccw(c143.038,32.106) 141.242,33.902 140.564,33.223 ccw(c141.054,32.733) 140.36,32.733 140.36,27.94 cw(c138.644,27.94) 139.858,26.726 139.827,26.695 cw(c139.582,26.941) 139.582,26.594 67.303,26.594 cw(c67.303,27.374) 66.751,26.822 cw(c66.935,27.006) 66.675,27.006 66.675,31.13 ccw(c64.135,31.13) 65.931,32.926 65.049,33.807 ccw(c63.884,32.642) 63.884,34.29 62.179,34.29 cw(c62.179,36.007) 60.965,34.793 60.63,35.128 cw(c61.488,35.987) 60.274,35.987 60.274,56.682 cw(c62.814,56.682) 61.018,58.478 61.849,59.309 cw(c63.627,57.531) 63.627,60.046 115.051,60.046 cw(c115.051,57.506) 116.847,59.302 118.306,57.843 cw(c116.51,56.047) 119.05,56.047 119.05,45.782 ccw(c121.59,45.782) 119.794,43.985 121.615,42.164 ccw(c123.394,43.942) 123.394,41.427 142.347,41.427 146.656,41.427 cw(c141.458,37.309) 147.904,35.752 147.481,35.197 147.381,35.087 cw(c146.253,36.214) 146.253,34.62
VCC_IN on Bottom Layer "VCC_IN_L04_P132" (solid, pour order 132): 69.418,63.017 65.608,63.017 65.43,63.195 65.43,111.125 71.831,117.526 122.784,117.526 123.215,117.094 123.215,112.471 120.675,109.931 73.101,109.931 69.647,106.477 69.647,63.246
GND on Bottom Layer "GND_L04_P128" (solid, pour order 128): 121.463,63.398 cw(c121.666,63.398) 121.666,63.602 123.901,63.602 cw(c123.901,63.348) 124.155,63.348 124.155,61.112 cw(c123.927,61.112) 123.927,60.884 121.691,60.884 cw(c121.691,61.112) 121.463,61.112
GND on Bottom Layer "GND_L04_P127" (solid, pour order 127): 129.87,71.73 cw(c129.997,71.73) 129.997,71.857 133.375,71.857 cw(c133.375,71.755) 133.477,71.755 133.477,68.377 cw(c133.35,68.377) 133.35,68.25 129.972,68.25 cw(c129.972,68.351) 129.87,68.351
GND on Bottom Layer "GND_L04_P126" (solid, pour order 126): 129.032,89.713 cw(c129.184,89.713) 129.184,89.865 133.172,89.865 cw(c133.172,89.713) 133.325,89.713 133.325,85.7 cw(c133.198,85.7) 133.198,85.573 129.159,85.573 cw(c129.159,85.7) 129.032,85.7
GND on Bottom Layer "Bottom Layer-GND 16" (solid, pour order 77): 83.031,79.639 86.281,79.639 87.732,81.09 87.732,98.146 94.594,105.008 106.9,105.008 110.474,101.434 113.249,98.659 113.249,81.039 111.324,79.114 111.324,76.365 111.324,76.065 113.224,77.965 113.224,79.189 115.173,81.139 115.173,104.133 109.959,109.347 90.78,109.347 80.874,99.441 80.874,81.026 81.385,80.514 82.157,80.514
RFGND on Layer 1 "RFGND_L02_P153" (solid, pour order 153): 146.253,34.635 143.013,34.635 ccw(c143.013,32.095) 141.217,33.891 140.538,33.213 ccw(c141.029,32.722) 140.335,32.722 140.335,27.93 cw(c138.618,27.93) 139.832,26.715 139.802,26.685 cw(c139.556,26.93) 139.556,26.583 67.278,26.583 cw(c67.278,27.364) 66.726,26.812 cw(c66.91,26.996) 66.65,26.996 66.65,31.119 ccw(c64.11,31.119) 65.906,32.915 65.024,33.797 ccw(c63.859,32.632) 63.859,34.28 62.154,34.28 cw(c62.154,35.997) 60.94,34.782 60.604,35.118 cw(c61.463,35.976) 60.249,35.976 60.249,56.672 cw(c62.789,56.672) 60.993,58.468 61.824,59.299 cw(c63.602,57.52) 63.602,60.035 115.026,60.035 cw(c115.026,57.495) 116.822,59.291 118.28,57.833 cw(c116.485,56.037) 119.024,56.037 119.024,45.771 ccw(c121.564,45.771) 119.768,43.975 121.59,42.154 ccw(c123.368,43.932) 123.368,41.417 142.322,41.417 146.631,41.417 cw(c141.432,37.299) 147.879,35.742 147.456,35.187 147.355,35.077 cw(c146.228,36.204) 146.228,34.61
GND on Layer 1 "GND_L02_P151" (solid, pour order 151): 64.033,117.424 62.343,117.424 ccw(c62.343,115.863) 61.239,116.967 60.409,116.136 ccw(c62.205,114.34) 59.665,114.34 59.665,61.834 ccw(c62.019,61.757) 60.3,60.147 115.331,60.147 cw(c115.331,57.607) 117.127,59.403 119.278,57.252 cw(c119.095,57.068) 119.355,57.068 119.355,46.061 ccw(c121.895,46.061) 120.099,44.265 122.758,41.605 147.061,41.605 ccw(c147.061,42.906) 147.98,41.986 147.98,114.238 ccw(c145.441,114.239) 147.236,116.035 145.745,117.526

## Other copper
Top Layer:
  pour cut-out: 112.037,39.093 cw(c112.576,39.632) 112.037,39.093 111.087,40.043 ccw(c111.626,40.582) 111.087,40.043 cw(c113.422,42.378) 110.119,42.378 110.119,45.225 cw(c110.882,45.225) 111.644,45.225 111.644,42.378 ccw(c113.422,42.378) 112.165,41.121 113.115,40.171 ccw(c112.576,39.632) 113.115,40.171 ccw(c114.372,41.428) 114.372,39.65 129.743,39.65 cw(c129.743,36.348) 132.078,38.683 132.584,38.177 ccw(c132.045,37.638) 132.584,38.177 cw(c130.249,35.842) 133.552,35.842 133.552,26.67 cw(c132.789,26.67) 132.027,26.67 132.027,35.842 ccw(c130.249,35.842) 131.506,37.099 cw(c132.045,37.638) 131.506,37.099 131,37.605 ccw(c129.743,36.348) 129.743,38.125 114.372,38.125 cw(c114.372,41.428)
  pour cut-out: 106.514,36.944 ccw(c107.053,37.483) 106.514,36.944 ccw(c108.849,39.279) 108.849,35.977 111.165,35.977 cw(c111.165,34.199) 112.422,35.456 ccw(c112.961,35.995) 112.495,35.392 ccw(c113.098,35.857) 112.559,35.318 cw(c111.302,34.061) 113.08,34.061 113.08,26.935 ccw(c113.842,26.935) 114.605,26.935 114.605,34.061 ccw(c111.302,34.061) 113.638,36.397 ccw(c113.098,35.857) 113.564,36.461 ccw(c112.961,35.995) 113.5,36.534 ccw(c111.165,34.199) 111.165,37.501 108.849,37.501 cw(c108.849,39.279) 107.592,38.022 106.362,39.252 cw(c105.823,38.713) 106.363,39.252 106.362,39.252 cw(c107.619,40.509) 105.842,40.509 105.842,42.746 ccw(c105.079,42.746) 104.317,42.746 104.317,40.509 ccw(c107.619,40.509) 105.284,38.174 ccw(c105.823,38.713) 105.285,38.173 105.284,38.174
  pour cut-out: 92.608,27.036 ccw(c93.37,27.036) 94.132,27.036 94.132,33.477 cw(c95.91,33.477) 94.653,34.734 ccw(c94.114,35.273) 94.654,34.735 94.653,34.734 96.086,36.167 ccw(c93.751,38.502) 97.053,38.502 97.053,40.155 ccw(c96.291,40.155) 95.529,40.155 95.529,38.502 cw(c93.751,38.502) 95.008,37.245 ccw(c95.547,36.706) 95.007,37.245 95.008,37.245 93.575,35.812 cw(c94.114,35.273) 93.575,35.813 93.575,35.812 ccw(c95.91,33.477) 92.608,33.477
  pour cut-out: 73.66,26.848 73.66,34.178 cw(c76.962,34.178) 74.627,36.513 cw(c75.166,35.974) 74.632,36.518 cw(c75.177,35.984) 74.638,36.524 cw(c76.973,34.188) 76.973,37.491 89.557,37.491 ccw(c89.557,37.657) 89.674,37.539 ccw(c89.557,37.657) 89.674,37.54 ccw(c88.417,38.797) 90.195,38.797 90.195,39.954 cw(c90.957,39.954) 91.72,39.954 91.72,38.797 cw(c88.417,38.797) 90.753,36.461 cw(c89.557,37.657) 89.557,35.966 76.973,35.966 ccw(c76.973,34.188) 75.716,35.445 cw(c75.177,35.984) 75.71,35.44 cw(c75.166,35.974) 75.705,35.435 ccw(c76.962,34.178) 75.184,34.178 75.184,26.848 cw(c74.422,26.848)

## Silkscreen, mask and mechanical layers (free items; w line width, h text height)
Top Overlay:
  lines w0.076: 114.732,110.261 113.106,110.261 113.106,114.529 114.732,114.529 ; 114.732,112.42 116.357,112.42 ; 114.732,112.42 114.732,116.688 116.357,116.688 116.357,112.42 ; 114.732,112.42 114.732,108.153 116.357,108.153 116.357,112.42
  text "ZYNQ7010+AD9363 SDR" at 68.021,114.997 h2.03
  text "SD" at 115.926,114.046 h0.76 r90
  text "Designed by 薛定谔的猫" at 68.021,112.121 h2.03
  text "QSPI" at 114.3,111.252 h0.76 r90
  text "JTAG" at 115.926,108.89 h0.76 r90
  text "GND" at 116.256,106.121 h0.76 r180
  text "3V3" at 116.256,103.53 h0.76 r180
  text "TDO" at 116.256,100.99 h0.76 r180
  text "TDI" at 116.256,98.374 h0.76 r180
  text "TMS" at 116.281,95.86 h0.76 r180
  text "1.5V" at 64.232,94.158 h2.03 r270
  text "TCK" at 116.23,93.396 h0.76 r180
  text "RXD" at 116.205,90.932 h0.76 r180
  text "TXD" at 116.23,88.316 h0.76 r180
  text "3.3V" at 64.257,85.164 h2.03 r270
  text "1.0V" at 64.232,76.327 h2.03 r270
  text "1.8V" at 64.232,67.132 h2.03 r270
  text "1.3V_A" at 64.453,55.728 h2.03 r270
  text "1.3V_B" at 64.427,45.72 h2.03 r270
Top Solder:
  lines w0.483: 74.422,26.848 74.422,29.134 74.422,34.178 cw(c76.962,34.178) 75.166,35.974 ; 75.177,35.984 cw(c76.973,34.188) 76.973,36.728 89.557,36.728 ccw(c89.557,37.657) 90.213,37 ccw(c88.417,38.797) 90.957,38.797 90.957,39.954 ; 93.32,26.899 93.32,29.159 93.32,33.339 cw(c95.86,33.339) 94.064,35.136 95.497,36.569 ccw(c93.701,38.365) 96.241,38.365 96.241,40.017 ; 105.131,42.684 105.131,40.448 ccw(c107.671,40.448) 105.875,38.651 107.104,37.422 ccw(c108.901,39.218) 108.901,36.678 111.216,36.678 cw(c111.216,34.138) 113.012,35.934 ; 110.858,45.275 110.858,42.429 ccw(c113.398,42.429) 111.602,40.633 112.553,39.682 ccw(c114.349,41.478) 114.349,38.938 129.72,38.938 cw(c129.72,36.398) 131.516,38.194 132.022,37.688 cw(c130.226,35.892) 132.766,35.892 132.766,29.058 132.766,26.721 ; 113.15,35.796 cw(c111.354,34) 113.894,34 113.894,29.134 113.894,26.873
Mechanical 1:
  the board outline again, w0.152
